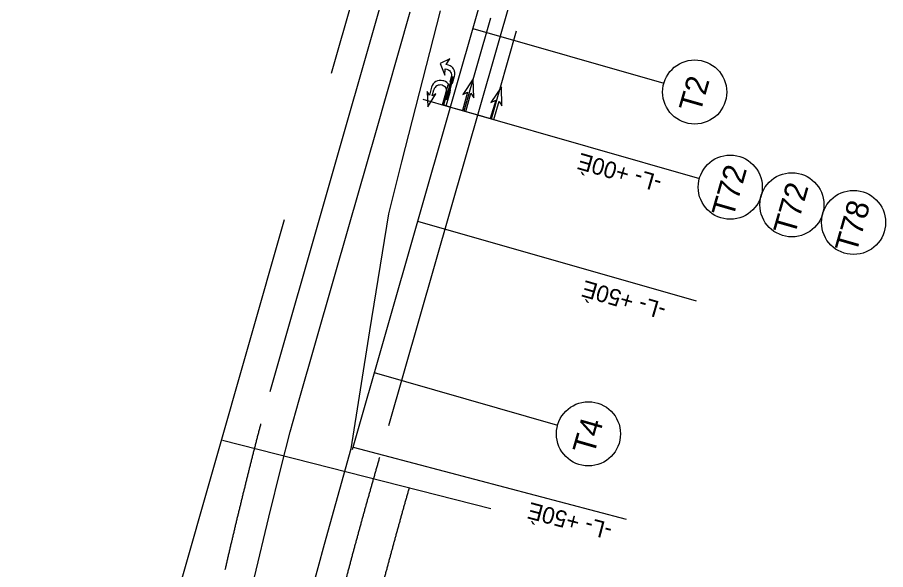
# Model space of a CAD drawing. Extents: x 1657109 to 2100937, y 684916 to 883211.
# Drawn here: x 2097739.1 to 2098104.6, y 689006 to 689238.5 of the extents above; entities that cross this region are included whole.
import ezdxf

# ---------------------------------------------------------------- set-up
doc = ezdxf.new("R2010")
doc.units = 0
for name, color, linetype in [('Prop CMT Pvmt Course 1', 7, 'Continuous'), ('Prop CMT Pvmt Gravel', 7, 'Continuous'), ('Prop Conc 1ft 6in Curb and Gutter', 7, 'Continuous'), ('Prop Conc 2ft 6in Curb and Gutter', 7, 'Continuous'), ('Prop Dimension', 7, 'Continuous'), ('Prop EOT', 7, 'Continuous'), ('Prop Lane Arrow CELL', 7, 'Continuous'), ('Prop Paved Shoulder', 7, 'Continuous'), ('Prop Sign E Chevron Right', 7, 'Continuous'), ('Scratch_Level_5', 7, 'Continuous'), ('Scratch_Level_7', 7, 'Continuous')]:
    doc.layers.add(name, color=color, linetype=linetype)

msp = doc.modelspace()

# ---------------------------------------------------------------- linework, layer by layer
at = {"layer": 'Prop CMT Pvmt Course 1'}
for p, q in [((2097913.5, 689209.21), (2097912.57, 689205.82)), ((2097918.58, 689211.77), (2097918.2, 689211.87)), ((2097912.57, 689205.82), (2097911.63, 689207.33)), ((2097911.63, 689207.33), (2097911.84, 689200.92)), ((2097911.84, 689200.92), (2097915.31, 689206.32)), ((2097913.73, 689205.5), (2097914.42, 689208.02)), ((2097915.31, 689206.32), (2097913.73, 689205.5)), ((2097919.84, 689206.52), (2097918.48, 689201.59)), ((2097919.64, 689201.27), (2097921.24, 689207.07)), ((2097918.48, 689201.59), (2097919.64, 689201.27))]:
    msp.add_line(p, q, dxfattribs=at)
for centre, radius, start, end in [((2097917.18, 689208.19), 3.82, 74.567, 164.567), ((2097917.13, 689207.27), 2.81, 74.567, 164.567), ((2097917.13, 689207.27), 2.81, 344.5671, 74.567), ((2097917.56, 689208.09), 3.82, 344.567, 74.567)]:
    msp.add_arc(centre, radius, start, end, dxfattribs=at)
at = {"layer": 'Prop CMT Pvmt Gravel'}
for p, q in [((2097930.83, 689233.84), (2098011.27, 689210.81)), ((2097907.58, 689152.71), (2098024.89, 689119.13)), ((2097889.36, 689088.94), (2097966.52, 689066.85)), ((2097880.4, 689057.52), (2097995.38, 689027.19))]:
    msp.add_line(p, q, dxfattribs=at)
msp.add_lwpolyline([(2097918.48, 689201.6), (2097932.27, 689197.65), (2098026.25, 689170.75)], dxfattribs=at)
for centre in [(2098024.25, 689207.1), (2098039.22, 689167.04), (2098065.18, 689159.61), (2098091.14, 689152.18), (2097979.5, 689063.14)]:
    msp.add_circle(centre, 13.5, dxfattribs=at)
at = {"layer": 'Prop Conc 1ft 6in Curb and Gutter'}
msp.add_line((2097907.61, 689152.7), (2097960.79, 689338.5), dxfattribs=at)
at = {"layer": 'Prop Conc 2ft 6in Curb and Gutter'}
msp.add_line((2097880.15, 689056.62), (2097907.61, 689152.7), dxfattribs=at)
at = {"layer": 'Prop Dimension'}
for p, q in [((2097909.83, 689204.08), (2097921.37, 689200.77)), ((2097921.37, 689200.77), (2097932.9, 689197.47)), ((2097932.9, 689197.47), (2097944.44, 689194.17))]:
    msp.add_line(p, q, dxfattribs=at)
for points in [[(2097921.37, 689200.77), (2097927.14, 689199.12), (2097938.35, 689238.31)], [(2097932.9, 689197.47), (2097938.67, 689195.82), (2097949.26, 689232.81)], [(2097921.37, 689200.77), (2097918.04, 689201.73), (2097920.43, 689210.08)]]:
    msp.add_lwpolyline(points, dxfattribs=at)
at = {"layer": 'Prop EOT'}
for p, q in [((2097845.45, 689080.92), (2097941.81, 689417.52)), ((2097895.44, 689066.61), (2097991.8, 689403.2))]:
    msp.add_line(p, q, dxfattribs=at)
for points in [[(2097826.59, 689005.96), (2097826.78, 689006.79), (2097826.97, 689007.63), (2097827.16, 689008.46), (2097827.36, 689009.29), (2097827.55, 689010.12), (2097827.74, 689010.96), (2097827.94, 689011.79), (2097828.13, 689012.62), (2097828.33, 689013.45), (2097828.52, 689014.28), (2097828.72, 689015.12), (2097828.91, 689015.95), (2097829.11, 689016.78), (2097829.3, 689017.61), (2097829.5, 689018.44), (2097829.7, 689019.28), (2097829.89, 689020.11), (2097830.09, 689020.94), (2097830.29, 689021.77), (2097830.49, 689022.6), (2097830.68, 689023.43), (2097830.88, 689024.27), (2097831.08, 689025.1), (2097831.28, 689025.93), (2097831.48, 689026.76), (2097831.68, 689027.59), (2097831.88, 689028.42), (2097832.08, 689029.25), (2097832.28, 689030.08), (2097832.48, 689030.91), (2097832.68, 689031.74), (2097832.88, 689032.57), (2097833.09, 689033.41), (2097833.29, 689034.24), (2097833.49, 689035.07), (2097833.69, 689035.9), (2097833.9, 689036.73), (2097834.1, 689037.56), (2097834.3, 689038.39), (2097834.51, 689039.22), (2097834.71, 689040.05), (2097834.92, 689040.88), (2097835.12, 689041.71), (2097835.33, 689042.54), (2097835.53, 689043.37), (2097835.74, 689044.2), (2097835.94, 689045.03), (2097836.15, 689045.86), (2097836.36, 689046.69), (2097836.56, 689047.52), (2097836.77, 689048.34), (2097836.98, 689049.17), (2097837.19, 689050), (2097837.4, 689050.83), (2097837.6, 689051.66), (2097837.81, 689052.49), (2097838.02, 689053.32), (2097838.23, 689054.15), (2097838.44, 689054.98), (2097838.65, 689055.81), (2097838.86, 689056.63), (2097839.07, 689057.46), (2097839.28, 689058.29), (2097839.5, 689059.12), (2097839.71, 689059.95), (2097839.92, 689060.78), (2097840.13, 689061.6), (2097840.34, 689062.43), (2097840.56, 689063.26), (2097840.77, 689064.09), (2097840.98, 689064.92), (2097841.2, 689065.74), (2097841.63, 689067.4)], [(2097875.33, 688993.74), (2097875.54, 688994.55), (2097875.75, 688995.36), (2097875.96, 688996.17), (2097876.17, 688996.98), (2097876.38, 688997.79), (2097876.6, 688998.6), (2097876.81, 688999.4), (2097877.02, 689000.21), (2097877.23, 689001.02), (2097877.45, 689001.83), (2097877.66, 689002.64), (2097877.87, 689003.45), (2097878.09, 689004.25), (2097878.3, 689005.06), (2097878.52, 689005.87), (2097878.73, 689006.68), (2097878.95, 689007.49), (2097879.16, 689008.29), (2097879.38, 689009.1), (2097879.59, 689009.91), (2097879.81, 689010.72), (2097880.03, 689011.52), (2097880.24, 689012.33), (2097880.46, 689013.14), (2097880.68, 689013.95), (2097880.9, 689014.75), (2097881.12, 689015.56), (2097881.33, 689016.37), (2097881.55, 689017.17), (2097881.77, 689017.98), (2097881.99, 689018.79), (2097882.21, 689019.59), (2097882.43, 689020.4), (2097882.65, 689021.21), (2097882.87, 689022.01), (2097883.09, 689022.82), (2097883.31, 689023.62), (2097883.54, 689024.43), (2097883.76, 689025.24), (2097883.98, 689026.04), (2097884.2, 689026.85), (2097884.42, 689027.65), (2097884.65, 689028.46), (2097884.87, 689029.27), (2097885.09, 689030.07), (2097885.32, 689030.88), (2097885.54, 689031.68), (2097885.77, 689032.49), (2097885.99, 689033.29), (2097886.22, 689034.1), (2097886.44, 689034.9), (2097886.67, 689035.71), (2097886.89, 689036.51), (2097887.12, 689037.32), (2097887.35, 689038.12), (2097887.57, 689038.92), (2097887.8, 689039.73), (2097888.03, 689040.53), (2097888.25, 689041.34), (2097888.48, 689042.14), (2097888.71, 689042.95), (2097888.94, 689043.75), (2097889.17, 689044.55), (2097889.4, 689045.36), (2097889.63, 689046.16), (2097889.86, 689046.97), (2097890.09, 689047.77), (2097890.32, 689048.57), (2097890.55, 689049.38), (2097890.78, 689050.18), (2097891.01, 689050.98), (2097891.24, 689051.79), (2097891.7, 689053.39)]]:
    msp.add_spline(points, degree=3, dxfattribs=at)
at = {"layer": 'Prop Lane Arrow CELL'}
msp.add_line((2097871.37, 689215.05), (2097930.27, 689420.82), dxfattribs=at)
at = {"layer": 'Prop Paved Shoulder'}
for points in [[(2097921.12, 689211.2), (2097922.27, 689210.87), (2097923.11, 689213.83), (2097923.24, 689214.38), (2097923.29, 689214.81), (2097923.27, 689215.31), (2097923.18, 689215.74), (2097923.07, 689216.09), (2097922.85, 689216.56), (2097922.63, 689216.89), (2097922.37, 689217.26), (2097922, 689217.66), (2097921.68, 689217.9), (2097921.23, 689218.19), (2097920.59, 689218.47), (2097919.67, 689218.73), (2097921.17, 689221.08), (2097917.08, 689219.06), (2097918.99, 689214.18), (2097919.15, 689216.92), (2097919.92, 689216.7), (2097920.34, 689216.56), (2097920.7, 689216.33), (2097920.97, 689216.1), (2097921.3, 689215.75), (2097921.5, 689215.46), (2097921.7, 689215), (2097921.79, 689214.5), (2097921.83, 689214.02), (2097921.75, 689213.39)], [(2097921.12, 689211.2), (2097922.27, 689210.87), (2097923.11, 689213.82), (2097923.24, 689214.38), (2097923.28, 689214.81), (2097923.27, 689215.3), (2097923.18, 689215.74), (2097923.07, 689216.08), (2097922.85, 689216.56), (2097922.63, 689216.89), (2097922.37, 689217.26), (2097921.99, 689217.66), (2097921.68, 689217.9), (2097921.23, 689218.19), (2097920.59, 689218.47), (2097919.67, 689218.73), (2097921.17, 689221.08), (2097917.08, 689219.06), (2097918.99, 689214.18), (2097919.15, 689216.92), (2097919.91, 689216.7), (2097920.34, 689216.55), (2097920.7, 689216.33), (2097920.97, 689216.1), (2097921.29, 689215.75), (2097921.5, 689215.46), (2097921.7, 689214.99), (2097921.79, 689214.5), (2097921.83, 689214.02), (2097921.75, 689213.39)]]:
    msp.add_lwpolyline(points, close=True, dxfattribs=at)
at = {"layer": 'Prop Sign E Chevron Right'}
for p, q in [((2097739.07, 688759.59), (2097851.61, 689153.37)), ((2097825.4, 689060.49), (2097938.38, 689031.75))]:
    msp.add_line(p, q, dxfattribs=at)
msp.add_spline([(2097890.35, 688989.86), (2097890.56, 688990.66), (2097890.77, 688991.47), (2097890.98, 688992.27), (2097891.19, 688993.08), (2097891.4, 688993.88), (2097891.61, 688994.69), (2097891.82, 688995.49), (2097892.03, 688996.29), (2097892.24, 688997.1), (2097892.46, 688997.9), (2097892.67, 688998.71), (2097892.88, 688999.51), (2097893.09, 689000.31), (2097893.31, 689001.12), (2097893.52, 689001.92), (2097893.73, 689002.72), (2097893.95, 689003.53), (2097894.16, 689004.33), (2097894.38, 689005.14), (2097894.59, 689005.94), (2097894.81, 689006.74), (2097895.02, 689007.54), (2097895.24, 689008.35), (2097895.46, 689009.15), (2097895.67, 689009.95), (2097895.89, 689010.76), (2097896.11, 689011.56), (2097896.32, 689012.36), (2097896.54, 689013.16), (2097896.76, 689013.97), (2097896.98, 689014.77), (2097897.2, 689015.57), (2097897.41, 689016.37), (2097897.63, 689017.18), (2097897.85, 689017.98), (2097898.07, 689018.78), (2097898.29, 689019.58), (2097898.51, 689020.38), (2097898.73, 689021.19), (2097898.95, 689021.99), (2097899.18, 689022.79), (2097899.4, 689023.59), (2097899.62, 689024.39), (2097899.84, 689025.19), (2097900.06, 689025.99), (2097900.29, 689026.79), (2097900.51, 689027.6), (2097900.73, 689028.4), (2097900.96, 689029.2), (2097901.18, 689030), (2097901.4, 689030.8), (2097901.63, 689031.6), (2097901.85, 689032.4), (2097902.08, 689033.2), (2097902.3, 689034), (2097902.53, 689034.8), (2097902.76, 689035.6), (2097902.98, 689036.4), (2097903.21, 689037.2), (2097903.43, 689038), (2097903.66, 689038.8), (2097903.89, 689039.6), (2097904.12, 689040.4), (2097904.13, 689040.46)], degree=3, dxfattribs=at)
at = {"layer": 'Scratch_Level_5'}
for points in [[(2097926.64, 689206.02), (2097928.62, 689207.02), (2097926.43, 689199.33), (2097927.87, 689198.92), (2097930.06, 689206.61), (2097931.21, 689204.72), (2097931.01, 689212.71)], [(2097926.64, 689206.02), (2097928.62, 689207.02), (2097926.43, 689199.33), (2097927.87, 689198.92), (2097930.06, 689206.61), (2097931.21, 689204.72), (2097931.01, 689212.71)], [(2097938.48, 689202.65), (2097940.47, 689203.63), (2097938.18, 689195.96), (2097939.62, 689195.53), (2097941.9, 689203.2), (2097943.03, 689201.3), (2097942.94, 689209.28)], [(2097938.48, 689202.65), (2097940.47, 689203.63), (2097938.18, 689195.96), (2097939.62, 689195.53), (2097941.9, 689203.2), (2097943.03, 689201.3), (2097942.94, 689209.28)]]:
    msp.add_lwpolyline(points, close=True, dxfattribs=at)
at = {"layer": 'Scratch_Level_7'}
for points in [[(2097838.95, 689002.86), (2097844.9, 689028.02), (2097850.1, 689049.09), (2097853.91, 689063.97), (2097857.71, 689077.41), (2097878.9, 689151.45), (2097889.95, 689190.03), (2097904.49, 689240.82)], [(2097917.13, 689241.23), (2097900.86, 689177.75), (2097895.26, 689155.87), (2097887.36, 689106.49), (2097879.43, 689056.83), (2097868.18, 689016.57), (2097862.96, 688996.84)]]:
    msp.add_lwpolyline(points, dxfattribs=at)

# ---------------------------------------------------------------- texts
at = {"layer": 'Prop CMT Pvmt Course 1'}
msp.add_text('l', height=9.82, rotation=164.567, dxfattribs=at).set_placement((2097923.86, 689213.31))
at = {"layer": 'Prop CMT Pvmt Gravel'}
for s, height, rotation, p in [('T2', 9.45, 74.0259, (2098026.55, 689197.94)), ('-L- +00È', 7, 164.0259, (2098010.91, 689171.61)), ('T72', 9.45, 74.0259, (2098040.35, 689153.79)), ('T72', 9.45, 74.0259, (2098066.3, 689146.36)), ('T78', 9.45, 74.0259, (2098092.24, 689138.86)), ('-L- +50È', 7, 164.0259, (2098012.73, 689117.95)), ('T4', 9.45, 74.0259, (2097981.79, 689053.95)), ('-L- +50È', 7, 165.2207, (2097990.02, 689025.22))]:
    msp.add_text(s, height=height, rotation=rotation, dxfattribs=at).set_placement(p)

doc.saveas('drawing.dxf')
